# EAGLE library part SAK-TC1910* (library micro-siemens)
32 bit TriCore based microcontroller/DSP which is mainly designed for automotive telematics applications. Source: http://www.infineon.com .. TC1910_DS_V1.0.pdf / TC1912_DS_V1.0.pdf
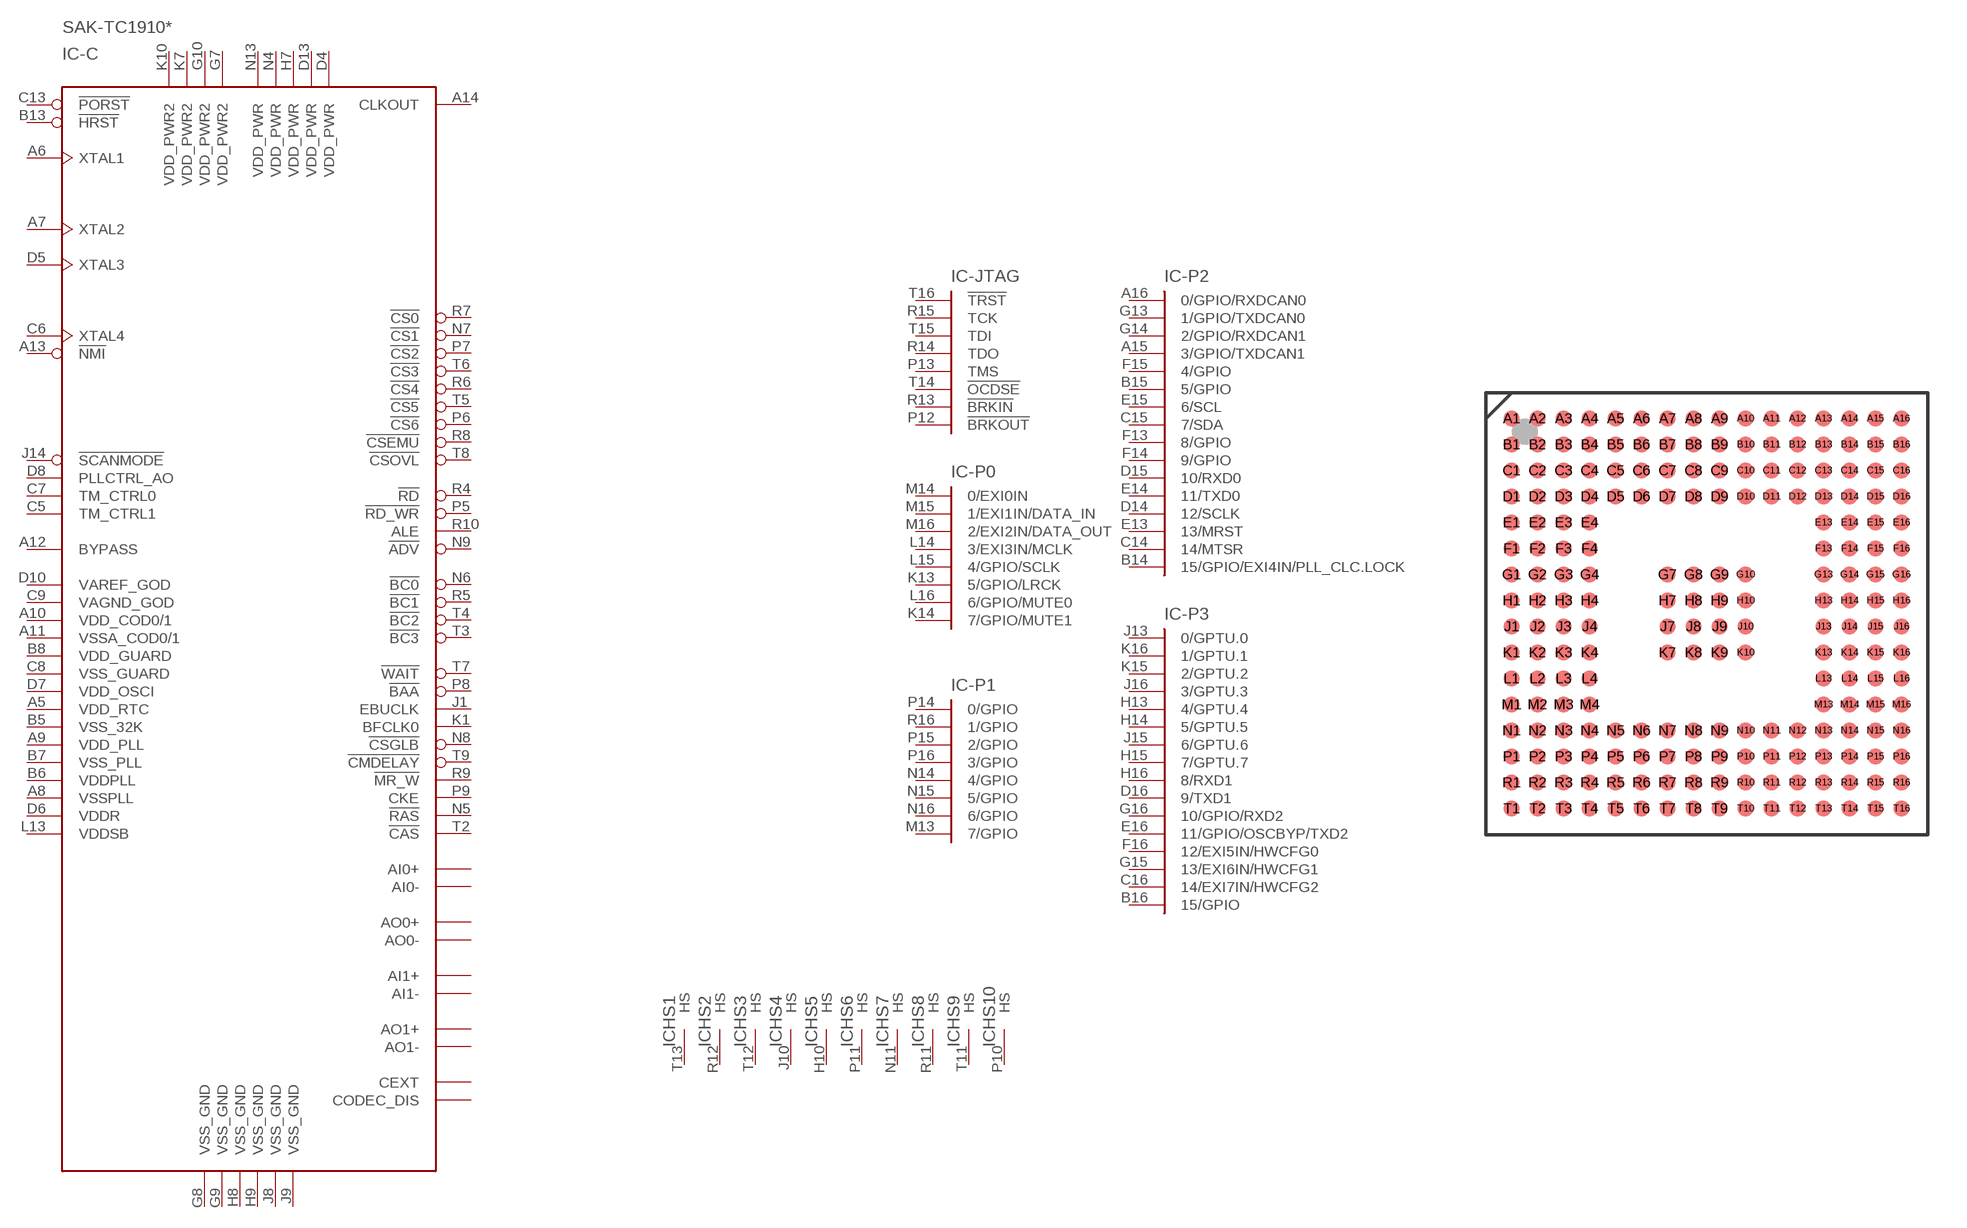
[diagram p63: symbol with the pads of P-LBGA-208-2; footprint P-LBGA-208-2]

Designator prefix IC; gates -C=TC1910 -JTAG=JTAG-OCSD -P0=PORT0-10_12 -P1=PORT1-10_12 -P2=PORT2-10_12 -P3=PORT3-10_12 HS1=HEATSINK HS2=HEATSINK HS3=HEATSINK HS4=HEATSINK HS5=HEATSINK HS6=HEATSINK HS7=HEATSINK HS8=HEATSINK HS9=HEATSINK HS10=HEATSINK HS11=HEATSINK HS12=HEATSINK HS13=HEATSINK HS14=HEATSINK HS15=HEATSINK HS0=HEATSINK -A=A23 -AD=AD31

## SAK-TC19100 (OC_FARNELL: unknown; OC_NEWARK: unknown), SAK-TC19102 (OC_FARNELL: unknown; OC_NEWARK: unknown)  [P-LBGA-208-2]
A1  -AD:AD20
A2  -AD:AD26
A3  -AD:AD28
A4  -AD:AD29
A5  -C:VDD_RTC  in
A6  -C:XTAL1  in
A7  -C:XTAL2  out
A8  -C:VSSPLL  in
A9  -C:VDD_PLL  in
A10  -C:VDD_COD0/1  in
A11  -C:VSSA_COD0/1  in
A12  -C:BYPASS  in
A13  -C:!NMI  in
A14  -C:CLKOUT  out
A15  -P2:3/GPIO/TXDCAN1
A16  -P2:0/GPIO/RXDCAN0
B1  -AD:AD17
B2  -AD:AD25
B3  -AD:AD27
B4  -AD:AD30
B5  -C:VSS_32K  in
B6  -C:VDDPLL  in
B7  -C:VSS_PLL  in
B8  -C:VDD_GUARD  in
B9  -C:AI0-  in
B10  -C:AI1-  in
B11  -C:AO1+  out
B12  -C:AO0-  out
B13  -C:!HRST
B14  -P2:15/GPIO/EXI4IN/PLL_CLC.LOCK
B15  -P2:5/GPIO
B16  -P3:15/GPIO
C1  -AD:AD13
C2  -AD:AD23
C3  -AD:AD24
C4  -AD:AD31
C5  -C:TM_CTRL1  in
C6  -C:XTAL4  out
C7  -C:TM_CTRL0  in
C8  -C:VSS_GUARD  in
C9  -C:VAGND_GOD  in
C10  -C:AI1+  in
C11  -C:AO0+  out
C12  -C:CODEC_DIS  in
C13  -C:!PORST  in
C14  -P2:14/MTSR
C15  -P2:7/SDA
C16  -P3:14/EXI7IN/HWCFG2
D1  -AD:AD9
D2  -AD:AD21
D3  -AD:AD22
D4  -C:VDD_PWR  in
D5  -C:XTAL3  in
D6  -C:VDDR  in
D7  -C:VDD_OSCI  in
D8  -C:PLLCTRL_AO  in
D9  -C:AI0+  in
D10  -C:VAREF_GOD  in
D11  -C:AO1-  out
D12  -C:CEXT  in
D13  -C:VDD_PWR  in
D14  -P2:12/SCLK
D15  -P2:10/RXD0
D16  -P3:9/TXD1
E1  -AD:AD8
E2  -AD:AD18
E3  -AD:AD16
E4  -AD:AD19
E13  -P2:13/MRST
E14  -P2:11/TXD0
E15  -P2:6/SCL
E16  -P3:11/GPIO/OSCBYP/TXD2
F1  -AD:AD7
F2  -AD:AD15
F3  -AD:AD14
F4  -AD:AD12
F13  -P2:8/GPIO
F14  -P2:9/GPIO
F15  -P2:4/GPIO
F16  -P3:12/EXI5IN/HWCFG0
G1  -AD:AD5
G2  -AD:AD11
G3  -AD:AD10
G4  -AD:AD6
G7  -C:VDD_PWR2  in
G8  -C:VSS_GND  in
G9  -C:VSS_GND  in
G10  -C:VDD_PWR2  in
G13  -P2:1/GPIO/TXDCAN0
G14  -P2:2/GPIO/RXDCAN1
G15  -P3:13/EXI6IN/HWCFG1
G16  -P3:10/GPIO/RXD2
H1  -AD:AD2
H2  -AD:AD4
H3  -AD:AD3
H4  -AD:AD0
H7  -C:VDD_PWR  in
H8  -C:VSS_GND  in
H9  -C:VSS_GND  in
H10  HS5:HS  in
H13  -P3:4/GPTU.4
H14  -P3:5/GPTU.5
H15  -P3:7/GPTU.7
H16  -P3:8/RXD1
J1  -C:EBUCLK  out
J2  -AD:AD1
J3  -A:A23  out
J4  -A:A21  out
J7  HS15:HS  in
J8  -C:VSS_GND  in
J9  -C:VSS_GND  in
J10  HS4:HS  in
J13  -P3:0/GPTU.0
J14  -C:!SCANMODE  in
J15  -P3:6/GPTU.6
J16  -P3:3/GPTU.3
K1  -C:BFCLK0  out
K2  -A:A22  out
K3  -A:A20  out
K4  -A:A19  out
K7  -C:VDD_PWR2  in
K8  HS14:HS  in
K9  HS13:HS  in
K10  -C:VDD_PWR2  in
K13  -P0:5/GPIO/LRCK
K14  -P0:7/GPIO/MUTE1
K15  -P3:2/GPTU.2
K16  -P3:1/GPTU.1
L1  -A:A17  out
L2  -A:A18  out
L3  -A:A16  out
L4  -A:A13  out
L13  -C:VDDSB  in
L14  -P0:3/EXI3IN/MCLK
L15  -P0:4/GPIO/SCLK
L16  -P0:6/GPIO/MUTE0
M1  -A:A15  out
M2  -A:A14  out
M3  -A:A12  out
M4  -A:A11  out
M13  -P1:7/GPIO
M14  -P0:0/EXI0IN
M15  -P0:1/EXI1IN/DATA_IN
M16  -P0:2/EXI2IN/DATA_OUT
N1  -A:A10  out
N2  -A:A9  out
N3  -A:A8  out
N4  -C:VDD_PWR  in
N5  -C:!RAS  out
N6  -C:!BC0
N7  -C:!CS1  out
N8  -C:!CSGLB  out
N9  -C:!ADV  out
N10  HS11:HS  in
N11  HS7:HS  in
N12  HS0:HS  in
N13  -C:VDD_PWR  in
N14  -P1:4/GPIO
N15  -P1:5/GPIO
N16  -P1:6/GPIO
P1  -A:A7  out
P2  -A:A6  out
P3  -A:A5  out
P4  -A:A1  out
P5  -C:!RD_WR
P6  -C:!CS6  out
P7  -C:!CS2  out
P8  -C:!BAA  out
P9  -C:CKE  out
P10  HS10:HS  in
P11  HS6:HS  in
P12  -JTAG:!BRKOUT  out
P13  -JTAG:TMS  in
P14  -P1:0/GPIO
P15  -P1:2/GPIO
P16  -P1:3/GPIO
R1  -A:A4  out
R2  -A:A3  out
R3  -A:A0  out
R4  -C:!RD
R5  -C:!BC1
R6  -C:!CS4  out
R7  -C:!CS0  out
R8  -C:!CSEMU  out
R9  -C:!MR_W  out
R10  -C:ALE  out
R11  HS8:HS  in
R12  HS2:HS  in
R13  -JTAG:!BRKIN  in
R14  -JTAG:TDO  out
R15  -JTAG:TCK  in
R16  -P1:1/GPIO
T1  -A:A2  out
T2  -C:!CAS  out
T3  -C:!BC3
T4  -C:!BC2
T5  -C:!CS5  out
T6  -C:!CS3  out
T7  -C:!WAIT
T8  -C:!CSOVL  out
T9  -C:!CMDELAY  in
T10  HS12:HS  in
T11  HS9:HS  in
T12  HS3:HS  in
T13  HS1:HS  in
T14  -JTAG:!OCDSE  in
T15  -JTAG:TDI  in
T16  -JTAG:!TRST  in

## Footprint P-LBGA-208-2 (pad centres in mm)
P-LBGA-208-2 Low Profile Plastic Ball Grid Array Package Source: http://www.infineon.com .. TC1130_DS_v031.pdf
smd 0.6 x 0.6: A1 -7.5,7.5; A2 -6.5,7.5; A3 -5.5,7.5; A4 -4.5,7.5; A5 -3.5,7.5; A6 -2.5,7.5; A7 -1.5,7.5; A8 -0.5,7.5; A9 0.5,7.5; A10 1.5,7.5; A11 2.5,7.5; A12 3.5,7.5; A13 4.5,7.5; A14 5.5,7.5; A15 6.5,7.5; A16 7.5,7.5; B1 -7.5,6.5; B2 -6.5,6.5; B3 -5.5,6.5; B4 -4.5,6.5; B5 -3.5,6.5; B6 -2.5,6.5; B7 -1.5,6.5; B8 -0.5,6.5; B9 0.5,6.5; B10 1.5,6.5; B11 2.5,6.5; B12 3.5,6.5; B13 4.5,6.5; B14 5.5,6.5; B15 6.5,6.5; B16 7.5,6.5; C1 -7.5,5.5; C2 -6.5,5.5; C3 -5.5,5.5; C4 -4.5,5.5; C5 -3.5,5.5; C6 -2.5,5.5; C7 -1.5,5.5; C8 -0.5,5.5; C9 0.5,5.5; C10 1.5,5.5; C11 2.5,5.5; C12 3.5,5.5; C13 4.5,5.5; C14 5.5,5.5; C15 6.5,5.5; C16 7.5,5.5; D1 -7.5,4.5; D2 -6.5,4.5; D3 -5.5,4.5; D4 -4.5,4.5; D5 -3.5,4.5; D6 -2.5,4.5; D7 -1.5,4.5; D8 -0.5,4.5; D9 0.5,4.5; D10 1.5,4.5; D11 2.5,4.5; D12 3.5,4.5; D13 4.5,4.5; D14 5.5,4.5; D15 6.5,4.5; D16 7.5,4.5; E1 -7.5,3.5; E2 -6.5,3.5; E3 -5.5,3.5; E4 -4.5,3.5; E13 4.5,3.5; E14 5.5,3.5; E15 6.5,3.5; E16 7.5,3.5; F1 -7.5,2.5; F2 -6.5,2.5; F3 -5.5,2.5; F4 -4.5,2.5; F13 4.5,2.5; F14 5.5,2.5; F15 6.5,2.5; F16 7.5,2.5; G1 -7.5,1.5; G2 -6.5,1.5; G3 -5.5,1.5; G4 -4.5,1.5; G7 -1.5,1.5; G8 -0.5,1.5; G9 0.5,1.5; G10 1.5,1.5; G13 4.5,1.5; G14 5.5,1.5; G15 6.5,1.5; G16 7.5,1.5; H1 -7.5,0.5; H2 -6.5,0.5; H3 -5.5,0.5; H4 -4.5,0.5; H7 -1.5,0.5; H8 -0.5,0.5; H9 0.5,0.5; H10 1.5,0.5; H13 4.5,0.5; H14 5.5,0.5; H15 6.5,0.5; H16 7.5,0.5; J1 -7.5,-0.5; J2 -6.5,-0.5; J3 -5.5,-0.5; J4 -4.5,-0.5; J7 -1.5,-0.5; J8 -0.5,-0.5; J9 0.5,-0.5; J10 1.5,-0.5; J13 4.5,-0.5; J14 5.5,-0.5; J15 6.5,-0.5; J16 7.5,-0.5; K1 -7.5,-1.5; K2 -6.5,-1.5; K3 -5.5,-1.5; K4 -4.5,-1.5; K7 -1.5,-1.5; K8 -0.5,-1.5; K9 0.5,-1.5; K10 1.5,-1.5; K13 4.5,-1.5; K14 5.5,-1.5; K15 6.5,-1.5; K16 7.5,-1.5; L1 -7.5,-2.5; L2 -6.5,-2.5; L3 -5.5,-2.5; L4 -4.5,-2.5; L13 4.5,-2.5; L14 5.5,-2.5; L15 6.5,-2.5; L16 7.5,-2.5; M1 -7.5,-3.5; M2 -6.5,-3.5; M3 -5.5,-3.5; M4 -4.5,-3.5; M13 4.5,-3.5; M14 5.5,-3.5; M15 6.5,-3.5; M16 7.5,-3.5; N1 -7.5,-4.5; N2 -6.5,-4.5; N3 -5.5,-4.5; N4 -4.5,-4.5; N5 -3.5,-4.5; N6 -2.5,-4.5; N7 -1.5,-4.5; N8 -0.5,-4.5; N9 0.5,-4.5; N10 1.5,-4.5; N11 2.5,-4.5; N12 3.5,-4.5; N13 4.5,-4.5; N14 5.5,-4.5; N15 6.5,-4.5; N16 7.5,-4.5; P1 -7.5,-5.5; P2 -6.5,-5.5; P3 -5.5,-5.5; P4 -4.5,-5.5; P5 -3.5,-5.5; P6 -2.5,-5.5; P7 -1.5,-5.5; P8 -0.5,-5.5; P9 0.5,-5.5; P10 1.5,-5.5; P11 2.5,-5.5; P12 3.5,-5.5; P13 4.5,-5.5; P14 5.5,-5.5; P15 6.5,-5.5; P16 7.5,-5.5; R1 -7.5,-6.5; R2 -6.5,-6.5; R3 -5.5,-6.5; R4 -4.5,-6.5; R5 -3.5,-6.5; R6 -2.5,-6.5; R7 -1.5,-6.5; R8 -0.5,-6.5; R9 0.5,-6.5; R10 1.5,-6.5; R11 2.5,-6.5; R12 3.5,-6.5; R13 4.5,-6.5; R14 5.5,-6.5; R15 6.5,-6.5; R16 7.5,-6.5; T1 -7.5,-7.5; T2 -6.5,-7.5; T3 -5.5,-7.5; T4 -4.5,-7.5; T5 -3.5,-7.5; T6 -2.5,-7.5; T7 -1.5,-7.5; T8 -0.5,-7.5; T9 0.5,-7.5; T10 1.5,-7.5; T11 2.5,-7.5; T12 3.5,-7.5; T13 4.5,-7.5; T14 5.5,-7.5; T15 6.5,-7.5; T16 7.5,-7.5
